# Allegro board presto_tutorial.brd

Outline 100 x 50 mm; copper layers: TOP, POWERPLANE_1, BOTTOM. Coordinates in mm from the lower left corner of the outline.
Outline path: 0,50 100,50 100,0 0,0 0,50

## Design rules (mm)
constraint set DEFAULT: min track width 0.127
net group DPD: nets D+ D-

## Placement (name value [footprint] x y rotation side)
C1  10uF  [0402-CAP]  12.95 37.08 270 top
C2  100uF  [1210]  6.86 32.51 0 top
C3  10uF  [0402-CAP]  35.05 26.67 180 top
C4  0.1uF  [0402-CAP]  22.35 68.84 0 top
C5  0.1uF  [0402-CAP]  35.29 68.84 0 top
C6  0.1uF  [0402-CAP]  48.24 68.84 0 top
C7  0.1uF  [0402-CAP]  61.18 68.84 0 top
C8  0.1uF  [0402-CAP]  74.13 68.84 0 top
C9  10uF  [0402-CAP]  10.16 22.35 180 top
IC1  PIC32MX440F512H  [SQFP-S-10X10-64]  20.83 25.91 90 top
JP1  -  [XTEND-DIGI-MODEM]  68.75 24.68 0 top
JP2  PIC 32 PROG  [1X06_LOCK]  12 15 0 top
MAIN_PWR  LED  [LED_LNJ]  4.83 27.69 0 top
NOREF  -  []  0 0 0 top
NOREF#2  -  [unnamed#2]  4 4 0 top
NOREF#3  -  [unnamed#2]  4 46 0 top
NOREF#4  -  []  0 0 0 top
NOREF#5  -  [unnamed#2]  96 4 0 top
NOREF#6  -  [unnamed#2]  96 46 0 top
R1  150  [0402-RES]  9.29 27.69 180 top
R2  56k  [0402-RES]  35.05 24.64 180 top
U1  LT1965EMS8E-1P5  [MSOP_8_ADI]  6.86 37.34 0 top
X1  USB-B  [USB-MICROB]  20 46 180 top
Y1  8MHz  [CRYSTAL-SMD]  19.49 37.22 270 top

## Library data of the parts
C1-C3 C9 = CAP NP
C4-C8 = CAP NP: room: PWR_3.3V
IC1 = PIC32MX440F512H
JP1 = XTEND-DIGI-MODEM
JP2 = M06_LOCK
MAIN_PWR = LED
R1 R2 = RESISTOR
U1 = LT1965EMS8E-1P5_1
X1 = USB-MICROB
Y1 = CRYSTAL

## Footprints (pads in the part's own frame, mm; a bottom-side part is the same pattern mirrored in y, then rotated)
1X06_LOCK
  rect 1.651x1.651 hole 0.914: 1(0,0)
  round 1.88 hole 1.016: 2(2.54,-0.254) 3(5.08,0) 4(7.62,-0.254) 5(10.16,0) 6(12.7,-0.254)
0402-CAP
  rect 0.7x0.9 smd: 1(-0.65,0) 2(0.65,0)
0402-RES
  rect 0.7x0.9 smd: 1(-0.65,0) 2(0.65,0)
1210
  rect 1.2x2 smd: 1(-1.6,0) 2(1.6,0)
CRYSTAL-SMD
  rect 1.1x1.9 smd: 1(-1.15,1.85) 2(-1.15,-1.85) 3(1.15,-1.85) 4(1.15,1.85)
LED_LNJ
  rect 0.445x0.95 smd: 1(-0.652,0) 2(0.652,0)
MSOP_8_ADI
  rect 1.31x0.431 smd: 1(-2.235,0.975) 2(-2.235,0.325) 3(-2.235,-0.325) 4(-2.235,-0.975) 5(2.235,-0.975) 6(2.235,-0.325) 7(2.235,0.325) 8(2.235,0.975)
SQFP-S-10X10-64
  rect 1.6x0.295 smd: 1(-5.6,3.75) 2(-5.6,3.25) 3(-5.6,2.75) 4(-5.6,2.25) 5(-5.6,1.75) 6(-5.6,1.25) 7(-5.6,0.75) 8(-5.6,0.25) 9(-5.6,-0.25) 10(-5.6,-0.75) 11(-5.6,-1.25) 12(-5.6,-1.75) 13(-5.6,-2.25) 14(-5.6,-2.75) 15(-5.6,-3.25) 16(-5.6,-3.75) 33(5.6,-3.75) 34(5.6,-3.25) 35(5.6,-2.75) 36(5.6,-2.25) 37(5.6,-1.75) 38(5.6,-1.25) 39(5.6,-0.75) 40(5.6,-0.25) 41(5.6,0.25) 42(5.6,0.75) 43(5.6,1.25) 44(5.6,1.75) 45(5.6,2.25) 46(5.6,2.75) 47(5.6,3.25) 48(5.6,3.75)
  rect 0.295x1.6 smd: 17(-3.75,-5.6) 18(-3.25,-5.6) 19(-2.75,-5.6) 20(-2.25,-5.6) 21(-1.75,-5.6) 22(-1.25,-5.6) 23(-0.75,-5.6) 24(-0.25,-5.6) 25(0.25,-5.6) 26(0.75,-5.6) 27(1.25,-5.6) 28(1.75,-5.6) 29(2.25,-5.6) 30(2.75,-5.6) 31(3.25,-5.6) 32(3.75,-5.6) 49(3.75,5.6) 50(3.25,5.6) 51(2.75,5.6) 52(2.25,5.6) 53(1.75,5.6) 54(1.25,5.6) 55(0.75,5.6) 56(0.25,5.6) 57(-0.25,5.6) 58(-0.75,5.6) 59(-1.25,5.6) 60(-1.75,5.6) 61(-2.25,5.6) 62(-2.75,5.6) 63(-3.25,5.6) 64(-3.75,5.6)
unnamed#2
  round 4.064 hole 3.81: (0,0)
USB-MICROB
  rect 0.35x1.4 smd: D+(0,2.65) D-(-0.65,2.65) GND(1.3,2.65) ID(0.65,2.65) VBUS(-1.3,2.65)
  rect 1.8x1.9 smd: MT1(-3.8,0) MT2(3.8,0)
  rect 2.1x1.6 smd: MT3(-3.1,2.55) MT4(3.1,2.55)
  rect 1.9x1.9 smd: P_1(-1.2,0) P_2(1.2,0)
XTEND-DIGI-MODEM
  round 0 hole 3.3 unplated: (-26.5,14.5) (-26.5,-14.5) (26.5,14.5) (26.5,-14.5)
  round 1.422 hole 0.7: 1(-27.5,9) 2(-25.5,9) 3(-27.5,7) 4(-25.5,7) 5(-27.5,5) 6(-25.5,5) 7(-27.5,3) 8(-25.5,3) 9(-27.5,1) 10(-25.5,1) 11(-27.5,-1) 12(-25.5,-1) 13(-27.5,-3) 14(-25.5,-3) 15(-27.5,-5) 16(-25.5,-5) 17(-27.5,-7) 18(-25.5,-7) 19(-27.5,-9) 20(-25.5,-9)

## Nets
3.3V: C2.1 C4.1 C5.1 C6.1 C7.1 C8.1 IC1.10 IC1.19 IC1.26 IC1.35 IC1.38 JP2.2 R1.1 R2.2 U1.1 U1.2 U1.3(SENSE/ADJ*)
GND: C1.2 C2.2 C3.2 C4.2 C5.2 C6.2 C7.2 C8.2 C9.2 IC1.9 IC1.20 IC1.25 IC1.41 JP1.1 JP2.3 MAIN_PWR.1(CATHODE) U1.4 U1.5 X1.GND Y1.2 Y1.4(GND_4)
VBUS: C1.1 IC1.34 JP1.2(VCC) U1.6 U1.7 U1.8 X1.VBUS
CTS: IC1.21 JP1.9
D+: IC1.37 X1.D+
D-: IC1.36 X1.D-
PROG0: IC1.17 JP2.5
PROG1: IC1.18 JP2.4
RESET: IC1.7(_MCLR) JP2.1
RTS: IC1.29 JP1.10
SHDN: IC1.59 JP1.7
URX: IC1.31 JP1.6
UTX: IC1.32 JP1.5
N01899: MAIN_PWR.2 R1.2
N02098: IC1.39 Y1.1
N02102: IC1.40 Y1.3
N02114: C9.1 IC1.56
N02189: C3.1 JP1.11 R2.1

Pads without a net: IC1 1 2 3 4 5 6 8 11 12 13 14 15 16 22 23 24 27 28 30 33 42 43 44 45 46 47 48 49 50 51 52 53 54 55 57 58 60 61 62 63 64; JP1 3 4 8 12 13 14 15 16 17 18 19 20; JP2 6; X1 ID MT1 MT2 MT3 MT4 P_1 P_2

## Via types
v1: diameter 0.61, hole 0.33, TOP to BOTTOM, 21 vias

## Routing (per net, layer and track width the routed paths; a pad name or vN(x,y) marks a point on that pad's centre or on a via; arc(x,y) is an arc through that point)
3.3V: length 16.7
  TOP w0.27: v1(23.58,32.74) IC1.35 ; v1(4.23,32.51) C2.1 ; v1(22.08,32.74) IC1.38 ; v1(27.66,26.66) IC1.26 ; U1.3 U1.2 U1.1 v1(3.54,38.31) ; IC1.10 v1(21.58,18.54) ; v1(28.2,23.16) IC1.19 ; v1(33.62,24.64) R2.2 ; v1(10.72,27.69) R1.1
  POWERPLANE_1 w0.381: 13.42,14.75 JP2.2 ; JP2.2 14.54,15.86 ; JP2.2 14.54,13.63 ; JP2.2 15.66,14.75
GND: length 43.7
  TOP w0.28: IC1.9 v1(21.08,21.54) ; IC1.25 v1(25.2,26.16)
  TOP w0.381: U1.4 v1(3.54,36.36) ; C3.2 v1(33.62,26.67) ; IC1.41 20.58,32.25 20.54,32.29 20.54,32.44 20.36,32.63 20.21,32.63 v1(19.3,33.53) 17.02,33.53 15.24,35.31 15.24,37.59 16,38.35 16.35,38.35 16.37,38.37 Y1.2 17.64,38.46 19.05,39.88 23.11,39.88 23.88,39.12 23.88,37.08 23.11,36.32 22.86,36.32 22.6,36.07 Y1.4 ; X1.GND v1(18.7,42.22) ; C2.2 v1(9.49,32.51) ; C9.2 v1(8.73,22.35) ; C1.2 v1(12.95,35.65) ; v1(25.2,23.66) IC1.20 ; MAIN_PWR.1 v1(3.52,27.69) ; U1.5 v1(10.18,36.36)
  BOTTOM w0.381: JP2.3 18.2,15 ; JP2.3 17.08,13.88 ; JP2.3 15.96,15 ; JP2.3 17.08,16.12 ; 41.25,32.79 JP1.1 ; JP1.1 42.14,33.68 ; JP1.1 41.25,34.57 ; JP1.1 40.36,33.68
VBUS: length 58.6
  TOP w0.127: 26.42,31.75 38.1,31.75 39.12,32.77 42.34,32.77 JP1.2 ; 26.42,31.75 24.64,29.97 23.53,29.97 ; 26.42,31.75 24.89,33.27 24.89,40.64 24.13,41.4 22.36,41.4 21.3,42.46 X1.VBUS ; 23.53,29.97 17.02,29.97 14.48,32.51 14.48,36.85 13.59,37.73 C1.1 12.31,37.73 12.24,37.66 U1.7 U1.8 ; 23.53,29.97 24.08,30.52 IC1.34
CTS: length 17.1
  TOP w0.127: IC1.21 29.24,24.16 32.77,27.69 39.24,27.69 JP1.9
D+: length 16
  TOP w0.127: IC1.37 22.58,32.5 22.7,32.63 22.7,34.64 24.38,36.32 24.38,39.37 23.11,40.64 20.47,40.64 20.2,40.92 20.2,42.26 20,42.46 X1.D+
D-: length 16
  TOP w0.127: IC1.36 23.08,32.5 22.95,32.63 22.95,34.53 24.64,36.22 24.64,39.48 23.22,40.89 20.58,40.89 20.45,41.02 20.45,42.26 20.65,42.46 X1.D-
PROG0: length 8.9
  TOP w0.127: IC1.17 26.43,19.27 JP2.5
PROG1: length 12.1
  TOP w0.127: IC1.18 25.44,22.66 25.15,22.37 25.15,18.92 25.02,18.8 23.67,18.8 JP2.4
RESET: length 10.9
  TOP w0.127: IC1.7 20.08,19.32 18.03,17.27 15.49,17.27 14.1,15.88 14.07,15.88 13.41,15.21 13.41,15.19 13.22,15 JP2.1
RTS: length 17.9
  TOP w0.127: JP1.10 42.26,26.67 40.89,26.67 39.41,28.16 IC1.29
SHDN: length 37.4
  TOP w0.127: JP1.7 41.89,28.31 42.54,28.31 42.93,28.7 44.2,28.7 44.45,28.96 44.45,30.23 43.94,30.73 40.89,30.73 40.39,31.24 26.67,31.24 23.88,28.45 22.61,28.45 18.82,24.66 IC1.59
URX: length 17.4
  TOP w0.127: JP1.6 42.28,28.7 39.62,28.7 39.17,29.16 IC1.31
UTX: length 15.7
  TOP w0.127: JP1.5 40.25,30.68 34.23,30.68 33.21,29.66 IC1.32
N01899: length 3.2
  TOP w0.127: MAIN_PWR.2 R1.2
N02098: length 8.5
  TOP w0.127: Y1.1 20.94,38.37 19.81,37.24 19.81,35.56 21.58,33.79 IC1.39
N02102: length 8.7
  TOP w0.127: IC1.40 21.08,33.03 20.78,33.32 20.6,33.32 20.5,33.21 20.32,33.21 20.14,33.39 20.14,33.57 20.25,33.68 20.25,33.86 20.07,34.04 19.89,34.04 19.78,33.93 19.6,33.93 19.42,34.11 19.42,34.29 19.53,34.4 19.53,34.58 19.26,34.84 19.08,34.84 18.62,34.39 18.44,34.39 18.26,34.57 18.26,34.75 18.72,35.2 18.72,35.38 18.04,36.07 Y1.3
N02114: length 6.4
  TOP w0.127: C9.1 10.81,23 13.97,26.16 IC1.56
N02189: length 8
  TOP w0.127: C3.1 R2.1 35.74,24.68 40.25,24.68 JP1.11

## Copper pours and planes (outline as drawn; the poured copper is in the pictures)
3.3V on POWERPLANE_1: 0.3,49.7 99.7,49.7 99.7,0.3 0.3,0.3
GND on BOTTOM: 0.3,49.7 99.7,49.7 99.7,0.3 0.3,0.3

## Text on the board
NCLEGEND-1-3: FIGURE | FINISHED_SIZE | 0.3302 | 0.7 | 0.9144 | 1.016 | 3.81 | 3.3 | DRILL CHART: TOP to BOTTOM | ALL UNITS ARE IN MILLIMETERS | DRILLED_SIZE | - | PLATED | NON-PLATED | QTY | 31 | 20 | 1 | 5 | 4
